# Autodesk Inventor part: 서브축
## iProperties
Company: 한국ATC센터
Created: 2014-12
Part Number: 서브축
Document SubType Name: Modeling
Designer: KYOUNG IL JANG
Density: 1 g/cm^3
Mass: 23.2871 g
Surface Area: 76.512 cm^2
Volume: 23.2871 cm^3
Author: KYOUNG IL JANG
